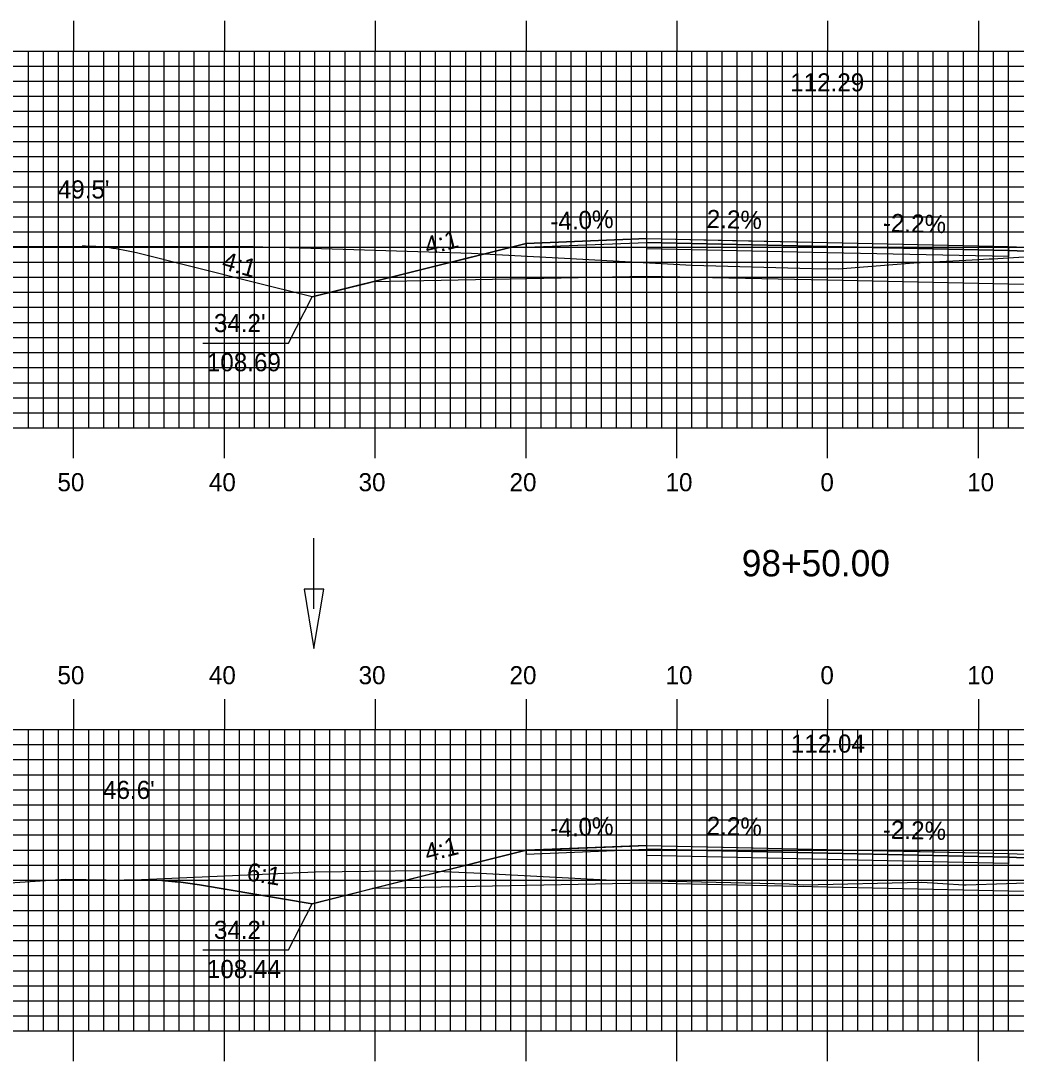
# Model space of a CAD drawing. Extents: x 1766120 to 1766463, y 442591 to 442811.
# Drawn here: x 1766231.9 to 1766297.9, y 442691.7 to 442760.7 of the extents above; entities that cross this region are included whole.
import ezdxf

# ---------------------------------------------------------------- set-up
doc = ezdxf.new("R2010")
doc.units = 0
for name, color, linetype in [('ANNOTATION', 7, 'Continuous'), ('D_Drainage_Ditch_Line', 7, 'Continuous'), ('D_Roadway_Centerline', 7, 'Continuous'), ('D_Roadway_Centerline_Text', 7, 'Continuous'), ('D_Roadway_Edge_Shoulder', 7, 'Continuous'), ('D_Roadway_Edge_TW', 7, 'Continuous'), ('D_Roadway_Pavement', 7, 'Continuous'), ('D_Roadway_SlopeLines', 7, 'Continuous'), ('D_Roadway_SubGrade', 7, 'Continuous'), ('D_Text_Standard', 7, 'Continuous'), ('H_V ANNOTATION', 7, 'Continuous'), ('MAJOR', 7, 'Continuous'), ('MINOR', 7, 'Continuous'), ('S_Roadway_Centerline', 7, 'Continuous')]:
    doc.layers.add(name, color=color, linetype=linetype)

msp = doc.modelspace()

# ---------------------------------------------------------------- linework, layer by layer
at = {"layer": 'ANNOTATION'}
for p, q in [((1766247.223, 442743.356), (1766239.567, 442745.27)), ((1766251.223, 442742.356), (1766247.223, 442743.356))]:
    msp.add_line(p, q, dxfattribs=at)
for points in [[(1766243.965, 442739.298), (1766249.657, 442739.298), (1766251.223, 442742.356)], [(1766243.965, 442699.048), (1766249.657, 442699.048), (1766251.223, 442702.106)]]:
    msp.add_lwpolyline(points, dxfattribs=at)
msp.add_arc((1766235.929, 442730.718), 15, 75.96376, 89.89516, dxfattribs=at)
at = {"layer": 'D_Drainage_Ditch_Line'}
msp.add_line((1766251.335, 442721.659), (1766251.335, 442726.358), dxfattribs=at)
msp.add_lwpolyline([(1766251.991, 442722.972), (1766250.679, 442722.972), (1766251.335, 442719.035)], close=True, dxfattribs=at)
at = {"layer": 'D_Roadway_Centerline'}
for points in [[(1766251.223, 442742.356), (1766255.058, 442743.315), (1766255.223, 442743.356), (1766265.397, 442745.9), (1766273.397, 442746.22), (1766279.088, 442746.095), (1766285.397, 442745.956), (1766285.4, 442745.956), (1766297.397, 442745.692), (1766305.397, 442745.372), (1766305.398, 442745.372), (1766309.87, 442744.254), (1766315.571, 442742.828), (1766317.332, 442742.388), (1766319.572, 442741.828), (1766327.356, 442743.774), (1766337.977, 442746.429), (1766339.227, 442746.695), (1766340.477, 442746.865), (1766340.646, 442746.875), (1766341.727, 442746.941), (1766342.638, 442746.928), (1766342.977, 442746.923)], [(1766238.755, 442703.664), (1766239.354, 442703.673), (1766240.006, 442703.683), (1766241.255, 442703.637), (1766242.13, 442703.56), (1766242.506, 442703.526), (1766243.756, 442703.351), (1766251.222, 442702.106), (1766251.223, 442702.106), (1766251.225, 442702.106), (1766253.641, 442702.711), (1766255.224, 442703.106), (1766265.396, 442705.65), (1766265.398, 442705.65), (1766271.24, 442705.884), (1766273.398, 442705.97), (1766278.461, 442705.859), (1766285.398, 442705.706), (1766289.591, 442705.614), (1766297.397, 442705.442), (1766297.399, 442705.442), (1766305.297, 442705.126)]]:
    msp.add_lwpolyline(points, dxfattribs=at)
at = {"layer": 'D_Roadway_Edge_Shoulder'}
for points in [[(1766273.397, 442746.22), (1766265.397, 442745.9), (1766265.397, 442745.65), (1766273.397, 442745.97)], [(1766297.397, 442745.692), (1766305.397, 442745.372), (1766305.397, 442745.122), (1766297.397, 442745.442)], [(1766273.397, 442705.97), (1766265.397, 442705.65), (1766265.397, 442705.4), (1766273.397, 442705.72)], [(1766297.397, 442705.442), (1766305.398, 442705.122), (1766305.398, 442704.872), (1766297.397, 442705.192)]]:
    msp.add_lwpolyline(points, close=True, dxfattribs=at)
at = {"layer": 'D_Roadway_Edge_TW'}
for points in [[(1766273.397, 442745.97), (1766273.397, 442746.22), (1766285.397, 442745.956), (1766297.397, 442745.692), (1766297.397, 442745.442), (1766285.397, 442745.706)], [(1766273.397, 442705.72), (1766273.397, 442705.97), (1766285.397, 442705.706), (1766297.397, 442705.442), (1766297.397, 442705.192), (1766285.397, 442705.456)]]:
    msp.add_lwpolyline(points, close=True, dxfattribs=at)
at = {"layer": 'D_Roadway_Pavement'}
for points in [[(1766273.397, 442745.553), (1766273.397, 442745.97), (1766285.397, 442745.706), (1766297.397, 442745.442), (1766297.397, 442745.025), (1766285.397, 442745.289)], [(1766273.397, 442705.303), (1766273.397, 442705.72), (1766285.397, 442705.456), (1766297.397, 442705.192), (1766297.397, 442704.775), (1766285.397, 442705.039)]]:
    msp.add_lwpolyline(points, close=True, dxfattribs=at)
at = {"layer": 'D_Roadway_SlopeLines'}
for points in [[(1766265.397, 442745.9), (1766251.223, 442742.356)], [(1766265.397, 442705.65), (1766251.223, 442702.106)], [(1766251.223, 442702.106), (1766243.756, 442703.351), (1766242.506, 442703.526), (1766241.256, 442703.637), (1766240.006, 442703.683), (1766238.756, 442703.664)]]:
    msp.add_lwpolyline(points, dxfattribs=at)
at = {"layer": 'D_Roadway_SubGrade'}
for points in [[(1766273.397, 442743.72), (1766255.223, 442743.356), (1766265.397, 442745.9), (1766265.397, 442745.65), (1766273.397, 442745.97), (1766285.397, 442745.706), (1766297.397, 442745.442), (1766305.397, 442745.122), (1766305.397, 442745.372), (1766315.571, 442742.828), (1766297.397, 442743.192), (1766285.397, 442743.456)], [(1766273.397, 442703.47), (1766255.223, 442703.106), (1766265.397, 442705.65), (1766265.397, 442705.4), (1766273.397, 442705.72), (1766285.397, 442705.456), (1766297.397, 442705.192), (1766305.398, 442704.872), (1766305.398, 442705.122), (1766315.571, 442702.578), (1766297.397, 442702.942), (1766285.397, 442703.206)]]:
    msp.add_lwpolyline(points, close=True, dxfattribs=at)
at = {"layer": 'MAJOR'}
for p, q in [((1766235.397, 442760.669), (1766235.397, 442758.665)), ((1766245.397, 442760.669), (1766245.397, 442758.665)), ((1766255.397, 442760.669), (1766255.397, 442758.665)), ((1766265.397, 442760.669), (1766265.397, 442758.665)), ((1766275.397, 442760.669), (1766275.397, 442758.665)), ((1766285.397, 442760.669), (1766285.397, 442758.665)), ((1766295.397, 442760.669), (1766295.397, 442758.665)), ((1766145.397, 442758.665), (1766425.397, 442758.665)), ((1766145.397, 442758.665), (1766425.397, 442758.665)), ((1766235.397, 442733.665), (1766235.397, 442758.665)), ((1766245.397, 442733.665), (1766245.397, 442758.665)), ((1766255.397, 442733.665), (1766255.397, 442758.665)), ((1766265.397, 442733.665), (1766265.397, 442758.665)), ((1766275.397, 442733.665), (1766275.397, 442758.665)), ((1766285.397, 442733.665), (1766285.397, 442758.665)), ((1766295.397, 442733.665), (1766295.397, 442758.665)), ((1766145.397, 442753.665), (1766425.397, 442753.665)), ((1766145.397, 442748.665), (1766425.397, 442748.665)), ((1766145.397, 442743.665), (1766425.397, 442743.665)), ((1766145.397, 442738.665), (1766425.397, 442738.665)), ((1766145.397, 442733.665), (1766425.397, 442733.665)), ((1766145.397, 442733.665), (1766425.397, 442733.665)), ((1766235.397, 442731.661), (1766235.397, 442733.665)), ((1766245.397, 442731.661), (1766245.397, 442733.665)), ((1766255.397, 442731.661), (1766255.397, 442733.665)), ((1766265.397, 442731.661), (1766265.397, 442733.665)), ((1766275.397, 442731.661), (1766275.397, 442733.665)), ((1766285.397, 442731.661), (1766285.397, 442733.665)), ((1766295.397, 442731.661), (1766295.397, 442733.665)), ((1766235.397, 442715.669), (1766235.397, 442713.665)), ((1766245.397, 442715.669), (1766245.397, 442713.665)), ((1766255.397, 442715.669), (1766255.397, 442713.665)), ((1766265.397, 442715.669), (1766265.397, 442713.665)), ((1766275.397, 442715.669), (1766275.397, 442713.665)), ((1766285.397, 442715.669), (1766285.397, 442713.665)), ((1766295.397, 442715.669), (1766295.397, 442713.665)), ((1766145.397, 442713.665), (1766425.397, 442713.665)), ((1766145.397, 442713.665), (1766425.397, 442713.665)), ((1766235.397, 442693.665), (1766235.397, 442713.665)), ((1766245.397, 442693.665), (1766245.397, 442713.665)), ((1766255.397, 442693.665), (1766255.397, 442713.665)), ((1766265.397, 442693.665), (1766265.397, 442713.665)), ((1766275.397, 442693.665), (1766275.397, 442713.665)), ((1766285.397, 442693.665), (1766285.397, 442713.665)), ((1766295.397, 442693.665), (1766295.397, 442713.665)), ((1766145.397, 442708.665), (1766425.397, 442708.665)), ((1766145.397, 442703.665), (1766425.397, 442703.665)), ((1766145.397, 442698.665), (1766425.397, 442698.665)), ((1766145.397, 442693.665), (1766425.397, 442693.665)), ((1766145.397, 442693.665), (1766425.397, 442693.665)), ((1766235.397, 442691.661), (1766235.397, 442693.665)), ((1766245.397, 442691.661), (1766245.397, 442693.665)), ((1766255.397, 442691.661), (1766255.397, 442693.665)), ((1766265.397, 442691.661), (1766265.397, 442693.665)), ((1766275.397, 442691.661), (1766275.397, 442693.665)), ((1766285.397, 442691.661), (1766285.397, 442693.665)), ((1766295.397, 442691.661), (1766295.397, 442693.665))]:
    msp.add_line(p, q, dxfattribs=at)
at = {"layer": 'MINOR'}
for p, q in [((1766232.397, 442733.665), (1766232.397, 442758.665)), ((1766233.397, 442733.665), (1766233.397, 442758.665)), ((1766234.397, 442733.665), (1766234.397, 442758.665)), ((1766236.397, 442733.665), (1766236.397, 442758.665)), ((1766237.397, 442733.665), (1766237.397, 442758.665)), ((1766238.397, 442733.665), (1766238.397, 442758.665)), ((1766239.397, 442733.665), (1766239.397, 442758.665)), ((1766240.397, 442733.665), (1766240.397, 442758.665)), ((1766241.397, 442733.665), (1766241.397, 442758.665)), ((1766242.397, 442733.665), (1766242.397, 442758.665)), ((1766243.397, 442733.665), (1766243.397, 442758.665)), ((1766244.397, 442733.665), (1766244.397, 442758.665)), ((1766246.397, 442733.665), (1766246.397, 442758.665)), ((1766247.397, 442733.665), (1766247.397, 442758.665)), ((1766248.397, 442733.665), (1766248.397, 442758.665)), ((1766249.397, 442733.665), (1766249.397, 442758.665)), ((1766250.397, 442733.665), (1766250.397, 442758.665)), ((1766251.397, 442733.665), (1766251.397, 442758.665)), ((1766252.397, 442733.665), (1766252.397, 442758.665)), ((1766253.397, 442733.665), (1766253.397, 442758.665)), ((1766254.397, 442733.665), (1766254.397, 442758.665)), ((1766256.397, 442733.665), (1766256.397, 442758.665)), ((1766257.397, 442733.665), (1766257.397, 442758.665)), ((1766258.397, 442733.665), (1766258.397, 442758.665)), ((1766259.397, 442733.665), (1766259.397, 442758.665)), ((1766260.397, 442733.665), (1766260.397, 442758.665)), ((1766261.397, 442733.665), (1766261.397, 442758.665)), ((1766262.397, 442733.665), (1766262.397, 442758.665)), ((1766263.397, 442733.665), (1766263.397, 442758.665)), ((1766264.397, 442733.665), (1766264.397, 442758.665)), ((1766266.397, 442733.665), (1766266.397, 442758.665)), ((1766267.397, 442733.665), (1766267.397, 442758.665)), ((1766268.397, 442733.665), (1766268.397, 442758.665)), ((1766269.397, 442733.665), (1766269.397, 442758.665)), ((1766270.397, 442733.665), (1766270.397, 442758.665)), ((1766271.397, 442733.665), (1766271.397, 442758.665)), ((1766272.397, 442733.665), (1766272.397, 442758.665)), ((1766273.397, 442733.665), (1766273.397, 442758.665)), ((1766274.397, 442733.665), (1766274.397, 442758.665)), ((1766276.397, 442733.665), (1766276.397, 442758.665)), ((1766277.397, 442733.665), (1766277.397, 442758.665)), ((1766278.397, 442733.665), (1766278.397, 442758.665)), ((1766279.397, 442733.665), (1766279.397, 442758.665)), ((1766280.397, 442733.665), (1766280.397, 442758.665)), ((1766281.397, 442733.665), (1766281.397, 442758.665)), ((1766282.397, 442733.665), (1766282.397, 442758.665)), ((1766283.397, 442733.665), (1766283.397, 442758.665)), ((1766284.397, 442733.665), (1766284.397, 442758.665)), ((1766286.397, 442733.665), (1766286.397, 442758.665)), ((1766287.397, 442733.665), (1766287.397, 442758.665)), ((1766288.397, 442733.665), (1766288.397, 442758.665)), ((1766289.397, 442733.665), (1766289.397, 442758.665)), ((1766290.397, 442733.665), (1766290.397, 442758.665)), ((1766291.397, 442733.665), (1766291.397, 442758.665)), ((1766292.397, 442733.665), (1766292.397, 442758.665)), ((1766293.397, 442733.665), (1766293.397, 442758.665)), ((1766294.397, 442733.665), (1766294.397, 442758.665)), ((1766296.397, 442733.665), (1766296.397, 442758.665)), ((1766297.397, 442733.665), (1766297.397, 442758.665)), ((1766145.397, 442757.665), (1766425.397, 442757.665)), ((1766145.397, 442756.665), (1766425.397, 442756.665)), ((1766145.397, 442755.665), (1766425.397, 442755.665)), ((1766145.397, 442754.665), (1766425.397, 442754.665)), ((1766145.397, 442752.665), (1766425.397, 442752.665)), ((1766145.397, 442751.665), (1766425.397, 442751.665)), ((1766145.397, 442750.665), (1766425.397, 442750.665)), ((1766145.397, 442749.665), (1766425.397, 442749.665)), ((1766145.397, 442747.665), (1766425.397, 442747.665)), ((1766145.397, 442746.665), (1766425.397, 442746.665)), ((1766145.397, 442745.665), (1766425.397, 442745.665)), ((1766145.397, 442744.665), (1766425.397, 442744.665)), ((1766145.397, 442742.665), (1766425.397, 442742.665)), ((1766145.397, 442741.665), (1766425.397, 442741.665)), ((1766145.397, 442740.665), (1766425.397, 442740.665)), ((1766145.397, 442739.665), (1766425.397, 442739.665)), ((1766145.397, 442737.665), (1766425.397, 442737.665)), ((1766145.397, 442736.665), (1766425.397, 442736.665)), ((1766145.397, 442735.665), (1766425.397, 442735.665)), ((1766145.397, 442734.665), (1766425.397, 442734.665)), ((1766232.397, 442693.665), (1766232.397, 442713.665)), ((1766233.397, 442693.665), (1766233.397, 442713.665)), ((1766234.397, 442693.665), (1766234.397, 442713.665)), ((1766236.397, 442693.665), (1766236.397, 442713.665)), ((1766237.397, 442693.665), (1766237.397, 442713.665)), ((1766238.397, 442693.665), (1766238.397, 442713.665)), ((1766239.397, 442693.665), (1766239.397, 442713.665)), ((1766240.397, 442693.665), (1766240.397, 442713.665)), ((1766241.397, 442693.665), (1766241.397, 442713.665)), ((1766242.397, 442693.665), (1766242.397, 442713.665)), ((1766243.397, 442693.665), (1766243.397, 442713.665)), ((1766244.397, 442693.665), (1766244.397, 442713.665)), ((1766246.397, 442693.665), (1766246.397, 442713.665)), ((1766247.397, 442693.665), (1766247.397, 442713.665)), ((1766248.397, 442693.665), (1766248.397, 442713.665)), ((1766249.397, 442693.665), (1766249.397, 442713.665)), ((1766250.397, 442693.665), (1766250.397, 442713.665)), ((1766251.397, 442693.665), (1766251.397, 442713.665)), ((1766252.397, 442693.665), (1766252.397, 442713.665)), ((1766253.397, 442693.665), (1766253.397, 442713.665)), ((1766254.397, 442693.665), (1766254.397, 442713.665)), ((1766256.397, 442693.665), (1766256.397, 442713.665)), ((1766257.397, 442693.665), (1766257.397, 442713.665)), ((1766258.397, 442693.665), (1766258.397, 442713.665)), ((1766259.397, 442693.665), (1766259.397, 442713.665)), ((1766260.397, 442693.665), (1766260.397, 442713.665)), ((1766261.397, 442693.665), (1766261.397, 442713.665)), ((1766262.397, 442693.665), (1766262.397, 442713.665)), ((1766263.397, 442693.665), (1766263.397, 442713.665)), ((1766264.397, 442693.665), (1766264.397, 442713.665)), ((1766266.397, 442693.665), (1766266.397, 442713.665)), ((1766267.397, 442693.665), (1766267.397, 442713.665)), ((1766268.397, 442693.665), (1766268.397, 442713.665)), ((1766269.397, 442693.665), (1766269.397, 442713.665)), ((1766270.397, 442693.665), (1766270.397, 442713.665)), ((1766271.397, 442693.665), (1766271.397, 442713.665)), ((1766272.397, 442693.665), (1766272.397, 442713.665)), ((1766273.397, 442693.665), (1766273.397, 442713.665)), ((1766274.397, 442693.665), (1766274.397, 442713.665)), ((1766276.397, 442693.665), (1766276.397, 442713.665)), ((1766277.397, 442693.665), (1766277.397, 442713.665)), ((1766278.397, 442693.665), (1766278.397, 442713.665)), ((1766279.397, 442693.665), (1766279.397, 442713.665)), ((1766280.397, 442693.665), (1766280.397, 442713.665)), ((1766281.397, 442693.665), (1766281.397, 442713.665)), ((1766282.397, 442693.665), (1766282.397, 442713.665)), ((1766283.397, 442693.665), (1766283.397, 442713.665)), ((1766284.397, 442693.665), (1766284.397, 442713.665)), ((1766286.397, 442693.665), (1766286.397, 442713.665)), ((1766287.397, 442693.665), (1766287.397, 442713.665)), ((1766288.397, 442693.665), (1766288.397, 442713.665)), ((1766289.397, 442693.665), (1766289.397, 442713.665)), ((1766290.397, 442693.665), (1766290.397, 442713.665)), ((1766291.397, 442693.665), (1766291.397, 442713.665)), ((1766292.397, 442693.665), (1766292.397, 442713.665)), ((1766293.397, 442693.665), (1766293.397, 442713.665)), ((1766294.397, 442693.665), (1766294.397, 442713.665)), ((1766296.397, 442693.665), (1766296.397, 442713.665)), ((1766297.397, 442693.665), (1766297.397, 442713.665)), ((1766145.397, 442712.665), (1766425.397, 442712.665)), ((1766145.397, 442711.665), (1766425.397, 442711.665)), ((1766145.397, 442710.665), (1766425.397, 442710.665)), ((1766145.397, 442709.665), (1766425.397, 442709.665)), ((1766145.397, 442707.665), (1766425.397, 442707.665)), ((1766145.397, 442706.665), (1766425.397, 442706.665)), ((1766145.397, 442705.665), (1766425.397, 442705.665)), ((1766145.397, 442704.665), (1766425.397, 442704.665)), ((1766145.397, 442702.665), (1766425.397, 442702.665)), ((1766145.397, 442701.665), (1766425.397, 442701.665)), ((1766145.397, 442700.665), (1766425.397, 442700.665)), ((1766145.397, 442699.665), (1766425.397, 442699.665)), ((1766145.397, 442697.665), (1766425.397, 442697.665)), ((1766145.397, 442696.665), (1766425.397, 442696.665)), ((1766145.397, 442695.665), (1766425.397, 442695.665)), ((1766145.397, 442694.665), (1766425.397, 442694.665))]:
    msp.add_line(p, q, dxfattribs=at)
at = {"layer": 'S_Roadway_Centerline'}
for points in [[(1766230.934, 442745.727), (1766247.306, 442745.697), (1766248.608, 442745.665), (1766249.719, 442745.639), (1766261.776, 442745.249), (1766267.937, 442744.933), (1766276.398, 442744.454), (1766284.342, 442744.246), (1766286.107, 442744.222), (1766291.11, 442744.614), (1766294.984, 442744.807), (1766296.097, 442744.875), (1766296.259, 442744.891), (1766296.326, 442744.889), (1766301.922, 442745.235), (1766304.461, 442745.468), (1766309.829, 442745.727), (1766321.206, 442745.648), (1766322.403, 442745.653), (1766322.934, 442745.654), (1766334.699, 442747.48), (1766342.489, 442746.906), (1766346.419, 442747.042)], [(1766226.069, 442703.15), (1766234.88, 442703.727), (1766238.915, 442703.662), (1766251.434, 442704.228), (1766258.481, 442704.318), (1766261.931, 442704.155), (1766271.139, 442703.664), (1766276.062, 442703.59), (1766282.847, 442703.419), (1766283.795, 442703.37), (1766291.647, 442703.543), (1766294.428, 442703.355), (1766294.589, 442703.353), (1766299.93, 442703.542)]]:
    msp.add_lwpolyline(points, dxfattribs=at)

# ---------------------------------------------------------------- texts
at = {"layer": 'ANNOTATION'}
for s, rotation, p in [('-4.0%', 2.29061, (1766267.029, 442746.767)), ('2.2%', 358.73972, (1766277.366, 442746.933)), ('-2.2%', 358.73967, (1766289.046, 442746.676)), ('4:1', 14.03872, (1766258.846, 442745.124)), ('4:1', 344.47224, (1766245.159, 442744.223)), ('-4.0%', 2.2906, (1766267.029, 442706.517)), ('2.2%', 358.7397, (1766277.366, 442706.683)), ('-2.2%', 358.73966, (1766289.045, 442706.426)), ('4:1', 14.03913, (1766258.845, 442704.873)), ('6:1', 350.5349, (1766246.822, 442703.668))]:
    msp.add_text(s, height=1.2, rotation=rotation, dxfattribs=at).set_placement(p)
for s, p in [("34.2'", (1766244.7, 442740.024)), ('108.69', (1766244.234, 442737.424)), ("34.2'", (1766244.7, 442699.774)), ('108.44', (1766244.234, 442697.174))]:
    msp.add_text(s, height=1.2, dxfattribs=at).set_placement(p)
at = {"layer": 'D_Roadway_Centerline'}
for s, p in [('C', (1766285.392, 442745.956)), ('L', (1766285.397, 442745.949)), ('C', (1766285.392, 442705.706)), ('L', (1766285.397, 442705.699))]:
    msp.add_text(s, height=0.0146, dxfattribs=at).set_placement(p)
at = {"layer": 'D_Roadway_Centerline_Text'}
for s, p in [('112.29', (1766282.914, 442755.986)), ('112.04', (1766282.957, 442712.128))]:
    msp.add_text(s, height=1.2, dxfattribs=at).set_placement(p)
at = {"layer": 'D_Text_Standard'}
for s, p in [("49.5'", (1766234.347, 442748.886)), ("46.6'", (1766237.349, 442709.056))]:
    msp.add_text(s, height=1.2, dxfattribs=at).set_placement(p)
at = {"layer": 'H_V ANNOTATION'}
for s, height, p in [('50', 1.2, (1766234.326, 442729.465)), ('40', 1.2, (1766244.369, 442729.465)), ('30', 1.2, (1766254.294, 442729.465)), ('20', 1.2, (1766264.305, 442729.465)), ('10', 1.2, (1766274.648, 442729.465)), ('0', 1.2, (1766284.915, 442729.465)), ('10', 1.2, (1766294.648, 442729.465)), ('98+50.00', 1.75, (1766279.701, 442723.821)), ('50', 1.2, (1766234.326, 442716.665)), ('40', 1.2, (1766244.369, 442716.665)), ('30', 1.2, (1766254.294, 442716.665)), ('20', 1.2, (1766264.305, 442716.665)), ('10', 1.2, (1766274.648, 442716.665)), ('0', 1.2, (1766284.915, 442716.665)), ('10', 1.2, (1766294.648, 442716.665))]:
    msp.add_text(s, height=height, dxfattribs=at).set_placement(p)

doc.saveas('drawing.dxf')
